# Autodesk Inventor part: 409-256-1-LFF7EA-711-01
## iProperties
Created: 2010-06
Part Number: 409-256-1-LFF7EA-711-01
Material: Sch40 CS PIPE SEAMLESS
Description: PIPE
Document SubType Name: Modeling
Designer: S. Boerckel
Engineer: Steve Boerckel
Mass: 4312.72 g
Surface Area: 1866.23 cm^2
Volume: 549.391 cm^3
Density: 7.85 g/cm^3
Cost Center: 4"
SMR: =<COST CENTER> - <Material>
Length: 10.563 in
Title: 3"
Author: S. Boerckel
Revision Number: A
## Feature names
1. Extrusion1
